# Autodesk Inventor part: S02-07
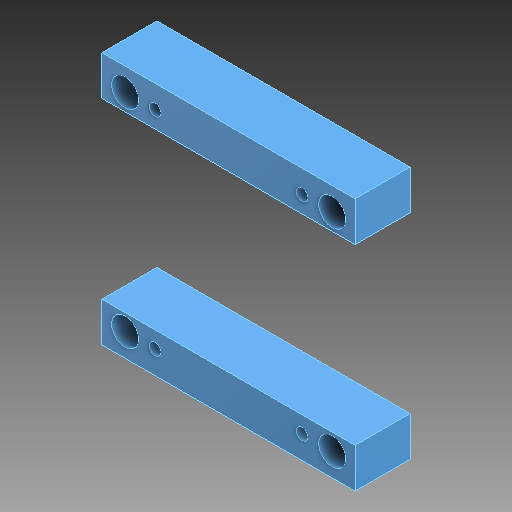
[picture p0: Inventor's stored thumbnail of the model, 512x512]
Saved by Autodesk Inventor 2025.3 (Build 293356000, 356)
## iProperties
Created: 2025-04
Part Number: S02-07
Material: Všeobecné
Document SubType Name: Modeling
Designer: Patrik
Density: 1 g/cm^3
Appearance: Výchozí
Description: Deska rozpěrná
Stock Number: F 70 /396 396/ 62/86/1730
User Status: 1730
Author: Patrik
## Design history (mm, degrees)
feature "Base1"
node "Těleso1"
